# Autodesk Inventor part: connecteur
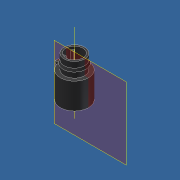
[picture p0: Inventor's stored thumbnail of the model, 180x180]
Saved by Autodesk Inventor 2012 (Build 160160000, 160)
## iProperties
Created: 2011-10
Part Number: connecteur
Material: Caoutchouc
Document SubType Name: Modeling
Designer: Laur
Mass: 0.383555 g
Surface Area: 3.08002 cm^2
Volume: 0.412425 cm^3
Density: 0.93 g/cm^3
Author: Laur
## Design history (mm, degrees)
sketch "Esquisse1"
  geometry: A1 r 4.3 centre (4.814, 0.4) between (0.544, -0.1) and (0.544, 0.9) reference; A2 r 4.3 centre (4.814, 0.4) between (0.544, 0.9) and (0.544, -0.1); 1 further point
  constraints: 2 point on circle, 1 centre point, 1 coincident
  node "Référence4"
node "Plan de construction1"
node "Plan de construction3"
extrude "grande base cyl" new body sketch "Esquisse1" stored distance "d0" = 10; taper "d1" = 0 deg
sketch "Esquisse2"
  geometry: L1 (-5.327, -0.5)-(-4.271, -0.5) reference; L2 (-4.271, 0.5)-(-5.327, 0.5) reference; L3 (-4.271, 0.5)-(-5.327, 0.5); L4 (-4.271, -0.5)-(-5.327, -0.5); C1 r 4.3 at (0, 0) reference; A1 r 5.35 centre (0, 0) between (-5.327, 0.5) and (-5.327, -0.5) reference; A2 r 4.3 centre (0, 0) between (-4.271, -0.5) and (-4.271, 0.5) reference; A3 r 4.3 centre (0, 0) between (-4.271, 0.5) and (-4.271, -0.5)
  constraints: 4 end point, 2 point on circle, 1 centre point, 1 coincident, 1 parallel
extrude "téton d'orientation" join sketch "Esquisse2" distance "d2" = 0.8; taper "d3" = 0 deg
node "Plan de construction2"
  node "Axe de construction1"
sketch "Esquisse3"
  geometry: L1 (-0.8, 5.327)-(-0.8, 5.327); L2 (-1.951, 5.81)-(-0.8, 5.327); L3 (-0.8, 4.271)-(-1.951, 5.81); L4 (-0.8, 5.327)-(-0.8, 4.271); L5 (-10.313, -4.296)-(0.786, -4.296); L6 (-1.951, -4.296)-(-8.728, -4.296); L7 (6.3, 2.6)-(10.7, 2.6); L8 (10.7, 2.6)-(10.7, 3.15); L9 (10.7, 3.15)-(6.3, 3.15); L10 (8.924, 3.15)-(8.1, 3.45); L11 (8.1, 3.45)-(8.1, 3.15); L12 (5.69, 0)-(11.512, 0); L13 (-14.678, 0)-(15.877, 0) reference; L14 (6.3, 2.6)-(6.3, 3.15); L15 (6.3, 2.6)-(6.3, 3.15); L16 (6.3, 4.3)-(6.3, -4.271) reference
  constraints: 28 end point, 4 point on line, 2 collinear, 2 perpendicular, 1 horizontal, 1 parallel
  dimensions: "d20" = 0.3 distance from line of L10.end L9; "d21" = 2.6 distance between parallel lines of L11 L8; "d22" = 160 deg angle of L10 L9; "d24" = 5.2 diameter of L7 L12; "d25" = 6.3 diameter of L9 L12; "d26" = 4.4 distance between parallel lines of L14 L8
revolve "clip male" sketch "Esquisse3" stored, may be unused: angle "d11" = 90 deg
sketch "Esquisse4"
  geometry: L1 (-1.428, 1.096)-(-1.765, 1.909); L2 (-1.765, 1.909)-(-2.301, 1.211); L3 (-2.301, 1.211)-(-1.428, 1.096); L4 (-1.428, -1.096)-(-2.301, -1.211); L5 (-2.301, -1.211)-(-1.765, -1.909); L6 (0, 0)-(-3.401, -2.61); L7 (0, 0)-(-4.099, 3.145); L8 (0, 0)-(-6.289, 0); L9 (-1.428, -1.096)-(-1.765, -1.909); A1 r 2.6 centre (0, 0) between (-1.765, 1.909) and (-2.301, 1.211)
  constraints: 18 end point, 4 point on circle, 2 point on line, 1 centre point, 3 other
  dimensions: "d12" = 75 deg angle of L6 L7; "d13" = 1.8 distance of L6.start L1.start; "d14" = 1.8 distance of L4.start L6.start (= d13); "d15" = 60 deg angle of L9 L4 (= d18); "d18" = 60 deg angle of L3 L1
extrude "Ergots détrompeurs" join sketch "Esquisse4" distance "d16" = 3.5; taper "d17" = 0 deg
node "Solide1"
node "Corps solides"
node "Corps surfaciques"
node "Référence7"
node "Référence8"
node "Boucle projetée4"
node "Référence9"
other parameters: "d19" = 0
